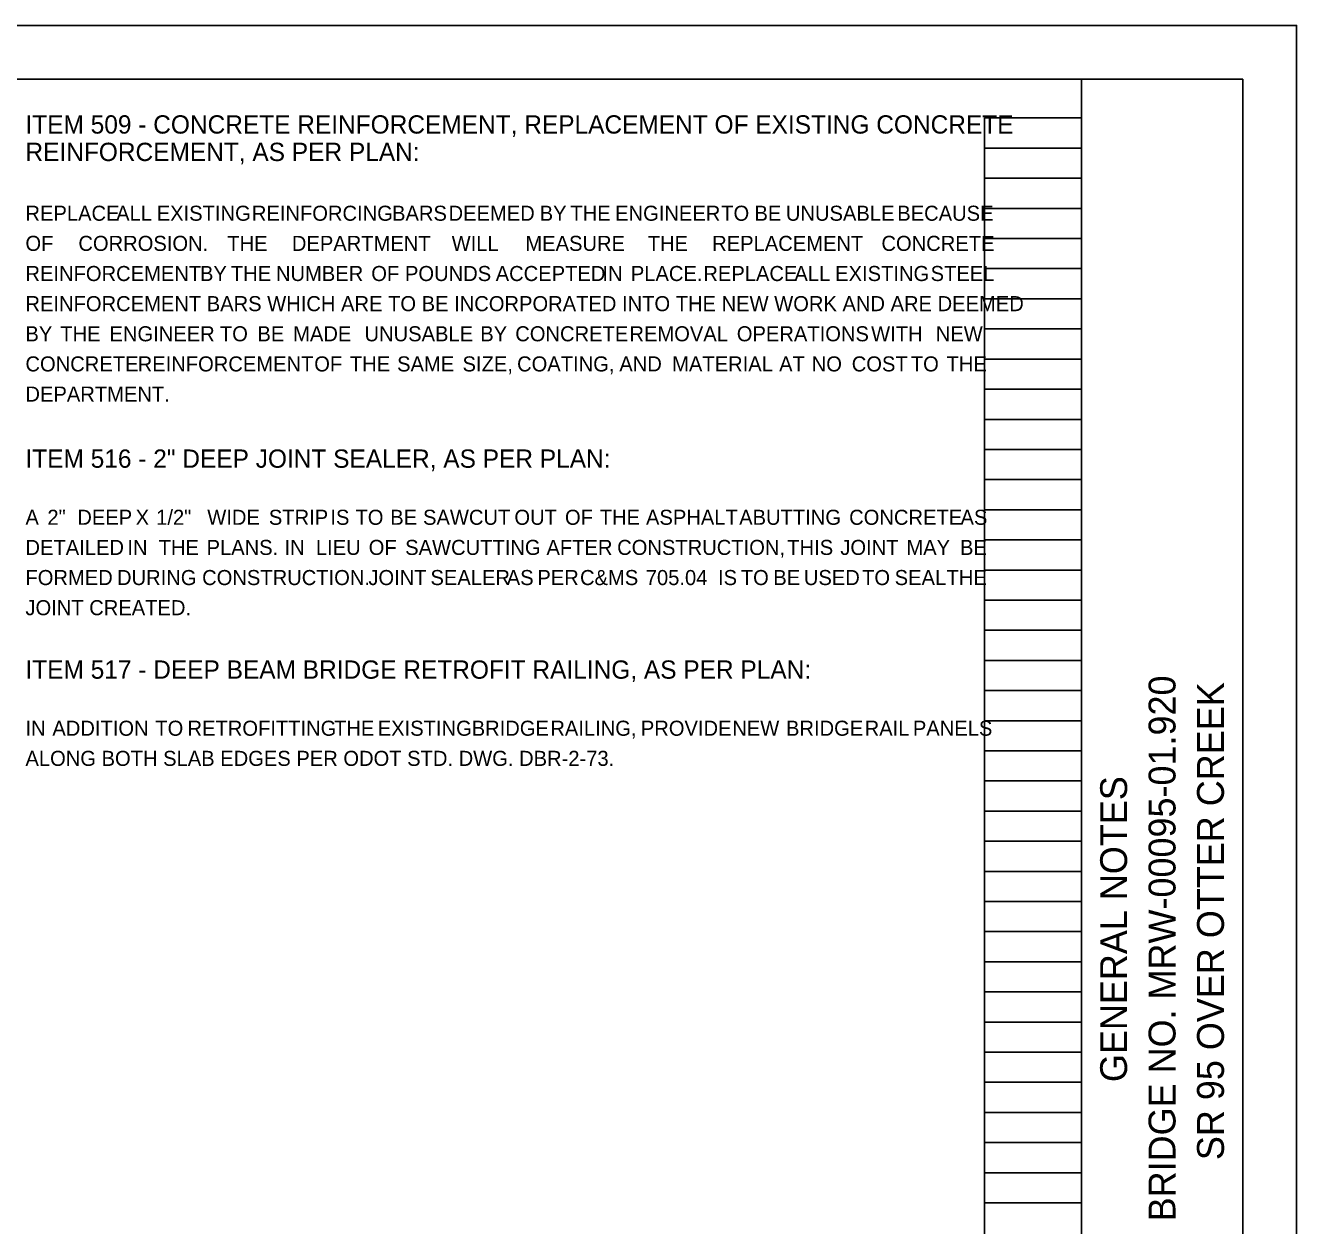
# Model space of a CAD drawing. Extents: x 0 to 64.5, y 0 to 22.
# Drawn here: x 22.19 to 34, y 10.85 to 22 of the extents above; entities that cross this region are included whole.
import ezdxf

# ---------------------------------------------------------------- set-up
doc = ezdxf.new("R2010")
doc.units = 0
for name, color, linetype in [('SC_Scratch1', 7, 'Continuous'), ('SH_Border', 7, 'Continuous'), ('SH_Cut_Line', 7, 'Continuous'), ('SH_Data', 7, 'Continuous'), ('SH_Text', 7, 'Continuous')]:
    doc.layers.add(name, color=color, linetype=linetype)

msp = doc.modelspace()

# ---------------------------------------------------------------- linework, layer by layer
at = {"layer": 'SC_Scratch1'}
for p, q in [((31.1, 0.98), (31.1, 21.14)), ((31.1, 21.14), (32, 21.14)), ((32, 0.98), (32, 21.14)), ((31.1, 20.86), (32, 20.86)), ((31.1, 20.58), (32, 20.58)), ((31.1, 20.3), (32, 20.3)), ((31.1, 20.02), (32, 20.02)), ((31.1, 19.74), (32, 19.74)), ((31.1, 19.46), (32, 19.46)), ((31.1, 19.18), (32, 19.18)), ((31.1, 18.9), (32, 18.9)), ((31.1, 18.62), (32, 18.62)), ((31.1, 18.34), (32, 18.34)), ((31.1, 18.06), (32, 18.06)), ((31.1, 17.78), (32, 17.78)), ((31.1, 17.5), (32, 17.5)), ((31.1, 17.22), (32, 17.22)), ((31.1, 16.94), (32, 16.94)), ((31.1, 16.66), (32, 16.66)), ((31.1, 16.38), (32, 16.38)), ((31.1, 16.1), (32, 16.1)), ((31.1, 15.82), (32, 15.82)), ((31.1, 15.54), (32, 15.54)), ((31.1, 15.26), (32, 15.26)), ((31.1, 14.98), (32, 14.98)), ((31.1, 14.7), (32, 14.7)), ((31.1, 14.42), (32, 14.42)), ((31.1, 14.14), (32, 14.14)), ((31.1, 13.86), (32, 13.86)), ((31.1, 13.58), (32, 13.58)), ((31.1, 13.3), (32, 13.3)), ((31.1, 13.02), (32, 13.02)), ((31.1, 12.74), (32, 12.74)), ((31.1, 12.46), (32, 12.46)), ((31.1, 12.18), (32, 12.18)), ((31.1, 11.9), (32, 11.9)), ((31.1, 11.62), (32, 11.62)), ((31.1, 11.34), (32, 11.34)), ((31.1, 11.06), (32, 11.06))]:
    msp.add_line(p, q, dxfattribs=at)
msp.add_lwpolyline([(0, 22), (34, 22), (34, 0), (0, 0)], close=True, dxfattribs=at)
at = {"layer": 'SH_Border'}
msp.add_line((32, 0.5), (32, 21.5), dxfattribs=at)
msp.add_lwpolyline([(1.5, 21.5), (33.5, 21.5), (33.5, 0.5), (1.5, 0.5)], close=True, dxfattribs=at)
at = {"layer": 'SH_Cut_Line'}
msp.add_lwpolyline([(0, 0), (34, 0), (34, 22), (0, 22)], close=True, dxfattribs=at)

# ---------------------------------------------------------------- texts
at = {"layer": 'SH_Data'}
for s, p in [('BRIDGE NO. MRW-00095-01.920', (32.875, 10.888)), ('SR 95 OVER OTTER CREEK', (33.325, 11.457)), ('GENERAL NOTES', (32.425, 12.182))]:
    msp.add_text(s, height=0.25, rotation=90, dxfattribs=at).set_placement(p)
at = {"layer": 'SH_Text'}
for s, height, p in [('ITEM 509 - CONCRETE REINFORCEMENT, REPLACEMENT OF EXISTING CONCRETE ', 0.17, (22.187, 20.995)), ('REINFORCEMENT, AS PER PLAN:', 0.17, (22.187, 20.74)), ('REPLACE ', 0.14, (22.187, 20.185)), ('ALL ', 0.14, (23.03, 20.185)), ('EXISTING ', 0.14, (23.407, 20.185)), ('REINFORCING ', 0.14, (24.291, 20.185)), ('BARS ', 0.14, (25.594, 20.185)), ('DEEMED ', 0.14, (26.119, 20.185)), ('BY ', 0.14, (26.966, 20.185)), ('THE ', 0.14, (27.251, 20.185)), ('ENGINEER ', 0.14, (27.667, 20.185)), ('TO ', 0.14, (28.653, 20.185)), ('BE ', 0.14, (28.962, 20.185)), ('UNUSABLE ', 0.14, (29.254, 20.185)), ('BECAUSE ', 0.14, (30.289, 20.185)), ('OF ', 0.14, (22.187, 19.905)), ('CORROSION. ', 0.14, (22.679, 19.905)), ('THE ', 0.14, (24.063, 19.905)), ('DEPARTMENT ', 0.14, (24.663, 19.905)), ('WILL ', 0.14, (26.148, 19.905)), ('MEASURE ', 0.14, (26.833, 19.905)), ('THE ', 0.14, (27.97, 19.905)), ('REPLACEMENT ', 0.14, (28.569, 19.905)), ('CONCRETE ', 0.14, (30.142, 19.905)), ('REINFORCEMENT ', 0.14, (22.187, 19.625)), ('BY ', 0.14, (23.809, 19.625)), ('THE ', 0.14, (24.096, 19.625)), ('NUMBER ', 0.14, (24.515, 19.625)), ('OF ', 0.14, (25.401, 19.625)), ('POUNDS ', 0.14, (25.714, 19.625)), ('ACCEPTED ', 0.14, (26.557, 19.625)), ('IN ', 0.14, (27.549, 19.625)), ('PLACE. ', 0.14, (27.813, 19.625)), ('REPLACE ', 0.14, (28.487, 19.625)), ('ALL ', 0.14, (29.333, 19.625)), ('EXISTING ', 0.14, (29.712, 19.625)), ('STEEL ', 0.14, (30.599, 19.625)), ('REINFORCEMENT BARS WHICH ARE TO BE INCORPORATED INTO THE NEW WORK AND ARE DEEMED ', 0.14, (22.187, 19.345)), ('BY ', 0.14, (22.187, 19.065)), ('THE ', 0.14, (22.511, 19.065)), ('ENGINEER ', 0.14, (22.968, 19.065)), ('TO ', 0.14, (23.994, 19.065)), ('BE ', 0.14, (24.343, 19.065)), ('MADE ', 0.14, (24.675, 19.065)), ('UNUSABLE ', 0.14, (25.338, 19.065)), ('BY ', 0.14, (26.414, 19.065)), ('CONCRETE ', 0.14, (26.739, 19.065)), ('REMOVAL ', 0.14, (27.8, 19.065)), ('OPERATIONS ', 0.14, (28.798, 19.065)), ('WITH ', 0.14, (30.046, 19.065)), ('NEW ', 0.14, (30.647, 19.065)), ('CONCRETE ', 0.14, (22.187, 18.785)), ('REINFORCEMENT ', 0.14, (23.23, 18.785)), ('OF ', 0.14, (24.871, 18.785)), ('THE ', 0.14, (25.202, 18.785)), ('SAME ', 0.14, (25.641, 18.785)), ('SIZE, ', 0.14, (26.249, 18.785)), ('COATING, ', 0.14, (26.756, 18.785)), ('AND ', 0.14, (27.706, 18.785)), ('MATERIAL ', 0.14, (28.197, 18.785)), ('AT ', 0.14, (29.191, 18.785)), ('NO ', 0.14, (29.494, 18.785)), ('COST ', 0.14, (29.866, 18.785)), ('TO ', 0.14, (30.415, 18.785)), ('THE ', 0.14, (30.747, 18.785)), ('DEPARTMENT.', 0.14, (22.187, 18.505)), ('ITEM 516 - 2" DEEP JOINT SEALER, AS PER PLAN:', 0.17, (22.187, 17.89)), ('A ', 0.14, (22.187, 17.36)), ('2" ', 0.14, (22.391, 17.36)), ('DEEP ', 0.14, (22.669, 17.36)), ('X ', 0.14, (23.211, 17.36)), ('1/2" ', 0.14, (23.402, 17.36)), ('WIDE ', 0.14, (23.877, 17.36)), ('STRIP ', 0.14, (24.449, 17.36)), ('IS ', 0.14, (25.021, 17.36)), ('TO ', 0.14, (25.254, 17.36)), ('BE ', 0.14, (25.577, 17.36)), ('SAWCUT ', 0.14, (25.882, 17.36)), ('OUT ', 0.14, (26.731, 17.36)), ('OF ', 0.14, (27.201, 17.36)), ('THE ', 0.14, (27.524, 17.36)), ('ASPHALT ', 0.14, (27.954, 17.36)), ('ABUTTING ', 0.14, (28.82, 17.36)), ('CONCRETE ', 0.14, (29.842, 17.36)), ('AS ', 0.14, (30.877, 17.36)), ('DETAILED ', 0.14, (22.187, 17.08)), ('IN ', 0.14, (23.134, 17.08)), ('THE ', 0.14, (23.425, 17.08)), ('PLANS. ', 0.14, (23.87, 17.08)), ('IN ', 0.14, (24.595, 17.08)), ('LIEU ', 0.14, (24.886, 17.08)), ('OF ', 0.14, (25.377, 17.08)), ('SAWCUTTING ', 0.14, (25.716, 17.08)), ('AFTER ', 0.14, (27.029, 17.08)), ('CONSTRUCTION, ', 0.14, (27.686, 17.08)), ('THIS ', 0.14, (29.267, 17.08)), ('JOINT ', 0.14, (29.76, 17.08)), ('MAY ', 0.14, (30.374, 17.08)), ('BE ', 0.14, (30.872, 17.08)), ('FORMED ', 0.14, (22.187, 16.8)), ('DURING ', 0.14, (23.038, 16.8)), ('CONSTRUCTION. ', 0.14, (23.829, 16.8)), ('JOINT ', 0.14, (25.374, 16.8)), ('SEALER ', 0.14, (25.951, 16.8)), ('AS ', 0.14, (26.66, 16.8)), ('PER ', 0.14, (26.944, 16.8)), ('C&MS ', 0.14, (27.341, 16.8)), ('705.04 ', 0.14, (27.952, 16.8)), ('IS ', 0.14, (28.623, 16.8)), ('TO ', 0.14, (28.835, 16.8)), ('BE ', 0.14, (29.137, 16.8)), ('USED ', 0.14, (29.421, 16.8)), ('TO ', 0.14, (29.962, 16.8)), ('SEAL ', 0.14, (30.265, 16.8)), ('THE ', 0.14, (30.747, 16.8)), ('JOINT CREATED.', 0.14, (22.187, 16.52)), ('ITEM 517 - DEEP BEAM BRIDGE RETROFIT RAILING, AS PER PLAN:', 0.17, (22.187, 15.93)), ('IN ', 0.14, (22.187, 15.4)), ('ADDITION ', 0.14, (22.437, 15.4)), ('TO ', 0.14, (23.394, 15.4)), ('RETROFITTING ', 0.14, (23.693, 15.4)), ('THE ', 0.14, (25.055, 15.4)), ('EXISTING ', 0.14, (25.461, 15.4)), ('BRIDGE ', 0.14, (26.334, 15.4)), ('RAILING, ', 0.14, (27.065, 15.4)), ('PROVIDE ', 0.14, (27.906, 15.4)), ('NEW ', 0.14, (28.756, 15.4)), ('BRIDGE ', 0.14, (29.255, 15.4)), ('RAIL ', 0.14, (29.986, 15.4)), ('PANELS ', 0.14, (30.434, 15.4)), ('ALONG BOTH SLAB EDGES PER ODOT STD. DWG. DBR-2-73.', 0.14, (22.187, 15.12))]:
    msp.add_text(s, height=height, dxfattribs=at).set_placement(p)

doc.saveas('drawing.dxf')
